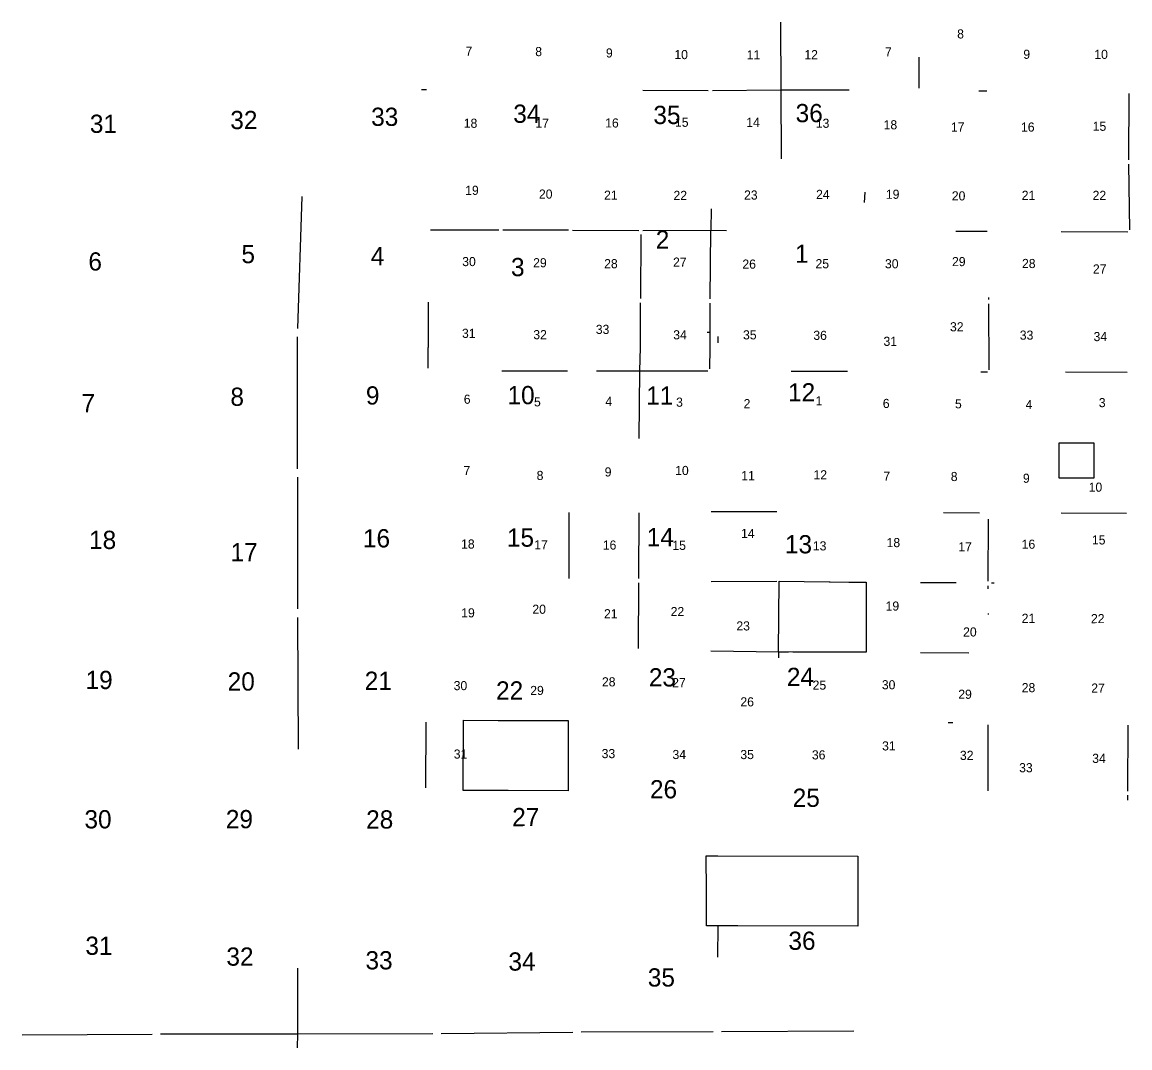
# Model space of a CAD drawing. Extents: x -2251611 to -2054719, y -2227156 to -2099355.
# Drawn here: x -2155950 to -2114262, y -2227040 to -2188443 of the extents above; entities that cross this region are included whole.
import ezdxf

# ---------------------------------------------------------------- set-up
doc = ezdxf.new("R2010")
doc.units = 0
for name, color, linetype in [('tdCoCorpBndry', 7, 'Continuous'), ('tdCoSectLinePart', 7, 'Continuous'), ('tdCoSectNmbr', 7, 'Continuous')]:
    doc.layers.add(name, color=color, linetype=linetype)

msp = doc.modelspace()

# ---------------------------------------------------------------- linework, layer by layer
at = {"layer": 'tdCoCorpBndry'}
for points in [[(-2116923, -2204273), (-2116554, -2204272), (-2116373, -2204271), (-2116187, -2204271), (-2115793, -2204271), (-2115620, -2204270), (-2115612, -2204270), (-2115614, -2205600), (-2116925, -2205597), (-2116926, -2204929), (-2116926, -2204752), (-2116925, -2204568), (-2116924, -2204386)], [(-2127462, -2209483), (-2125572, -2209504), (-2125548, -2209505), (-2125542, -2209505), (-2125537, -2209505), (-2124834, -2209517), (-2124190, -2209521), (-2124191, -2212150), (-2124838, -2212147), (-2126942, -2212144), (-2127479, -2212137), (-2127467, -2210795)], [(-2139345, -2214711), (-2138030, -2214717), (-2135399, -2214723), (-2135403, -2217364), (-2137663, -2217360), (-2137849, -2217360), (-2138035, -2217360), (-2139355, -2217351)], [(-2130202, -2219808), (-2129771, -2219810), (-2124498, -2219826), (-2124500, -2221125), (-2124496, -2222464), (-2129021, -2222452), (-2130200, -2222449), (-2130199, -2221152)]]:
    msp.add_lwpolyline(points, close=True, dxfattribs=at)
at = {"layer": 'tdCoSectLinePart'}
for points in [[(-2127404, -2188443), (-2127393, -2190994)], [(-2122186, -2190931), (-2122189, -2189765)], [(-2140920, -2190981), (-2140735, -2190981)], [(-2132589, -2191000), (-2130131, -2191011)], [(-2129973, -2191011), (-2127393, -2190994)], [(-2127393, -2190994), (-2124824, -2190987)], [(-2127393, -2190994), (-2127387, -2193583)], [(-2119945, -2191028), (-2119639, -2191030)], [(-2114304, -2193622), (-2114291, -2191133)], [(-2114262, -2196262), (-2114303, -2193781)], [(-2124236, -2194846), (-2124256, -2195228)], [(-2145579, -2199969), (-2145406, -2195008)], [(-2130025, -2195473), (-2130029, -2196274)], [(-2140581, -2196261), (-2138013, -2196257)], [(-2137855, -2196257), (-2135392, -2196264)], [(-2135234, -2196265), (-2132745, -2196285)], [(-2132667, -2196438), (-2132683, -2198848)], [(-2132587, -2196285), (-2130029, -2196274)], [(-2130051, -2198859), (-2130029, -2196274)], [(-2130029, -2196274), (-2129444, -2196282)], [(-2120813, -2196307), (-2119638, -2196314)], [(-2116850, -2196318), (-2114333, -2196332)], [(-2140665, -2201458), (-2140664, -2200703), (-2140663, -2200661), (-2140658, -2198979)], [(-2132706, -2201565), (-2132682, -2200687), (-2132682, -2200651), (-2132682, -2200598), (-2132684, -2199007)], [(-2130068, -2201484), (-2130058, -2200702), (-2130060, -2200646), (-2130052, -2199017)], [(-2119570, -2198881), (-2119570, -2198799)], [(-2119551, -2201528), (-2119570, -2199039)], [(-2130175, -2200105), (-2130056, -2200103)], [(-2129765, -2200268), (-2129766, -2200505)], [(-2145581, -2205254), (-2145584, -2200286)], [(-2137902, -2201560), (-2135420, -2201564)], [(-2134332, -2201565), (-2132706, -2201565)], [(-2132729, -2204105), (-2132706, -2201565)], [(-2132706, -2201565), (-2130142, -2201558)], [(-2127009, -2201576), (-2124882, -2201574)], [(-2119871, -2201601), (-2119620, -2201602)], [(-2116681, -2201605), (-2114358, -2201614)], [(-2145581, -2205570), (-2145581, -2210525)], [(-2135369, -2209378), (-2135363, -2206899)], [(-2132744, -2209381), (-2132732, -2206904)], [(-2130022, -2206855), (-2127545, -2206860)], [(-2121277, -2206892), (-2119925, -2206903)], [(-2116852, -2206913), (-2114383, -2206914)], [(-2119589, -2209477), (-2119579, -2207142)], [(-2132753, -2212013), (-2132745, -2209539)], [(-2130017, -2209495), (-2127543, -2209484)], [(-2122144, -2209523), (-2120798, -2209533)], [(-2119589, -2209763), (-2119589, -2209649)], [(-2119468, -2209541), (-2119373, -2209542)], [(-2119587, -2210737), (-2119587, -2210689)], [(-2145581, -2210841), (-2145565, -2215804)], [(-2130035, -2212095), (-2127468, -2212143)], [(-2127469, -2212365), (-2127468, -2212143)], [(-2127468, -2212143), (-2127468, -2212137)], [(-2127468, -2212143), (-2127114, -2212143)], [(-2122138, -2212158), (-2120323, -2212174)], [(-2140752, -2214786), (-2140769, -2217261)], [(-2121100, -2214797), (-2120929, -2214798)], [(-2119600, -2217363), (-2119596, -2214888)], [(-2114334, -2217376), (-2114331, -2214895)], [(-2114335, -2217720), (-2114334, -2217534)], [(-2129774, -2222450), (-2129777, -2223633)], [(-2145580, -2226511), (-2145578, -2224042)], [(-2155950, -2226544), (-2151058, -2226519)], [(-2150741, -2226517), (-2145580, -2226511)], [(-2145590, -2227040), (-2145580, -2226511)], [(-2145580, -2226511), (-2140496, -2226498)], [(-2140179, -2226496), (-2135224, -2226444)], [(-2134909, -2226442), (-2129943, -2226428)], [(-2129627, -2226427), (-2124651, -2226402)]]:
    msp.add_lwpolyline(points, dxfattribs=at)

# ---------------------------------------------------------------- texts
at = {"layer": 'tdCoSectNmbr'}
for s, height, rotation, p in [('8', 343, 0.0063, (-2120761, -2189057)), ('7', 343, 0.0009, (-2139261, -2189704)), ('8', 343, 0.0017, (-2136639, -2189722)), ('9', 343, 0.0024, (-2133979, -2189773)), ('7', 343, 0.0055, (-2123478, -2189734)), ('10', 343.2, 0.0032, (-2131404, -2189834)), ('11', 343.2, 0.004, (-2128683, -2189846)), ('12', 343.2, 0.0046, (-2126511, -2189837)), ('9', 343, 0.007, (-2118271, -2189823)), ('10', 343.2, 0.0078, (-2115599, -2189825)), ('36', 686.4, 0.0197, (-2126839, -2192208)), ('31', 686.4, 0.0158, (-2153401, -2192610)), ('32', 686.4, 0.0166, (-2148117, -2192468)), ('33', 686.4, 0.0174, (-2142815, -2192347)), ('34', 686.4, 0.0182, (-2137467, -2192232)), ('35', 686.4, 0.0189, (-2132193, -2192277)), ('18', 343.2, 0.0008, (-2139330, -2192418)), ('17', 343.2, 0.0016, (-2136633, -2192418)), ('16', 343.2, 0.0024, (-2134008, -2192407)), ('15', 343.2, 0.0032, (-2131381, -2192381)), ('14', 343.2, 0.0039, (-2128697, -2192382)), ('13', 343.2, 0.0047, (-2126081, -2192418)), ('18', 343.2, 0.0054, (-2123528, -2192477)), ('17', 343.2, 0.0062, (-2120996, -2192560)), ('16', 343.2, 0.007, (-2118359, -2192560)), ('15', 343.2, 0.0077, (-2115661, -2192532)), ('19', 343.2, 0.0009, (-2139277, -2194942)), ('20', 343.2, 0.0016, (-2136501, -2195084)), ('21', 343.2, 0.0024, (-2134050, -2195126)), ('22', 343.2, 0.0031, (-2131437, -2195134)), ('23', 343.2, 0.0039, (-2128782, -2195120)), ('24', 343.2, 0.0047, (-2126071, -2195097)), ('19', 343.2, 0.0055, (-2123444, -2195091)), ('20', 343.2, 0.0062, (-2120962, -2195151)), ('21', 343.2, 0.0069, (-2118331, -2195129)), ('22', 343.2, 0.0077, (-2115664, -2195133)), ('2', 686, 0.0188, (-2132104, -2196969)), ('5', 686, 0.0166, (-2147697, -2197513)), ('4', 686, 0.0173, (-2142832, -2197591)), ('1', 686, 0.0196, (-2126864, -2197499)), ('6', 686, 0.0157, (-2153457, -2197790)), ('30', 343.2, 0.0008, (-2139388, -2197624)), ('3', 686, 0.018, (-2137552, -2198002)), ('29', 343.2, 0.0016, (-2136719, -2197668)), ('27', 343.2, 0.0032, (-2131453, -2197645)), ('29', 343.2, 0.0062, (-2120955, -2197625)), ('28', 343.2, 0.0069, (-2118321, -2197696)), ('28', 343.2, 0.0024, (-2134047, -2197703)), ('26', 343.2, 0.0039, (-2128845, -2197719)), ('25', 343.2, 0.0047, (-2126092, -2197704)), ('30', 343.2, 0.0054, (-2123478, -2197707)), ('27', 343.2, 0.0077, (-2115652, -2197903)), ('33', 343.2, 0.0024, (-2134362, -2200176)), ('32', 343.2, 0.0062, (-2121031, -2200078)), ('31', 343.2, 0.0008, (-2139397, -2200324)), ('32', 343.2, 0.0016, (-2136713, -2200374)), ('34', 343.2, 0.0031, (-2131446, -2200380)), ('35', 343.2, 0.0039, (-2128820, -2200381)), ('36', 343.2, 0.0047, (-2126175, -2200399)), ('33', 343.2, 0.0069, (-2118404, -2200392)), ('34', 343.2, 0.0077, (-2115628, -2200446)), ('31', 343.2, 0.0054, (-2123534, -2200624)), ('8', 686, 0.0164, (-2148112, -2202881)), ('9', 686, 0.0172, (-2143012, -2202833)), ('10', 686.4, 0.0179, (-2137684, -2202820)), ('11', 686.4, 0.0187, (-2132465, -2202836)), ('12', 686.4, 0.0195, (-2127126, -2202716)), ('7', 686, 0.0156, (-2153715, -2203122)), ('6', 343, 0.0008, (-2139329, -2202802)), ('5', 343, 0.0016, (-2136686, -2202902)), ('4', 343, 0.0023, (-2134001, -2202884)), ('3', 343, 0.0032, (-2131338, -2202914)), ('2', 343, 0.0039, (-2128798, -2202970)), ('1', 343, 0.0046, (-2126088, -2202864)), ('6', 343, 0.0054, (-2123560, -2202962)), ('5', 343, 0.0062, (-2120843, -2202976)), ('4', 343, 0.0069, (-2118186, -2203003)), ('3', 343, 0.0077, (-2115430, -2202931)), ('7', 343, 0.0008, (-2139339, -2205487)), ('9', 343, 0.0023, (-2134025, -2205538)), ('10', 343.2, 0.0031, (-2131375, -2205485)), ('8', 343, 0.0016, (-2136587, -2205672)), ('11', 343.2, 0.0038, (-2128886, -2205678)), ('12', 343.2, 0.0046, (-2126168, -2205647)), ('7', 343, 0.0054, (-2123535, -2205698)), ('8', 343, 0.0061, (-2121001, -2205712)), ('9', 343, 0.0069, (-2118286, -2205777)), ('10', 343.2, 0.0077, (-2115812, -2206113)), ('18', 686.4, 0.0155, (-2153432, -2208268)), ('16', 686.4, 0.0171, (-2143124, -2208209)), ('15', 686.4, 0.0178, (-2137706, -2208182)), ('14', 686.4, 0.0186, (-2132442, -2208162)), ('14', 343.2, 0.0038, (-2128894, -2207854)), ('13', 686.4, 0.0193, (-2127243, -2208433)), ('15', 343.2, 0.0076, (-2115689, -2208098)), ('17', 686.4, 0.0163, (-2148107, -2208730)), ('18', 343.2, 0.0007, (-2139431, -2208252)), ('17', 343.2, 0.0015, (-2136676, -2208280)), ('16', 343.2, 0.0022, (-2134097, -2208291)), ('15', 343.2, 0.003, (-2131480, -2208303)), ('13', 343.2, 0.0046, (-2126192, -2208322)), ('18', 343.2, 0.0053, (-2123417, -2208199)), ('17', 343.2, 0.0062, (-2120717, -2208356)), ('16', 343.2, 0.0068, (-2118334, -2208259)), ('19', 343.2, 0.0053, (-2123453, -2210586)), ('19', 343.2, 0.0007, (-2139426, -2210842)), ('20', 343.2, 0.0015, (-2136748, -2210706)), ('21', 343.2, 0.0023, (-2134053, -2210876)), ('22', 343.2, 0.003, (-2131544, -2210794)), ('23', 343.2, 0.0038, (-2129070, -2211333)), ('21', 343.2, 0.0068, (-2118333, -2211047)), ('22', 343.2, 0.0076, (-2115726, -2211059)), ('20', 343.2, 0.0062, (-2120537, -2211561)), ('23', 686.4, 0.0185, (-2132364, -2213440)), ('24', 686.4, 0.0193, (-2127171, -2213424)), ('19', 686.4, 0.0155, (-2153563, -2213539)), ('20', 686.4, 0.0162, (-2148215, -2213596)), ('21', 686.4, 0.017, (-2143056, -2213569)), ('28', 343.2, 0.0022, (-2134130, -2213438)), ('27', 343.2, 0.003, (-2131485, -2213469)), ('30', 343.2, 0.0007, (-2139710, -2213580)), ('22', 686.4, 0.0178, (-2138114, -2213935)), ('29', 343.2, 0.0015, (-2136828, -2213763)), ('25', 343.2, 0.0045, (-2126201, -2213563)), ('30', 343.2, 0.0053, (-2123596, -2213548)), ('29', 343.2, 0.0061, (-2120719, -2213905)), ('28', 343.2, 0.0068, (-2118331, -2213656)), ('27', 343.2, 0.0075, (-2115714, -2213673)), ('26', 343.2, 0.0037, (-2128919, -2214191)), ('31', 343.2, 0.0053, (-2123586, -2215849)), ('31', 343.2, 0.0006, (-2139707, -2216156)), ('33', 343.2, 0.0022, (-2134141, -2216138)), ('34', 343.2, 0.003, (-2131475, -2216173)), ('35', 343.2, 0.0037, (-2128920, -2216174)), ('36', 343.2, 0.0045, (-2126228, -2216186)), ('32', 343.2, 0.0061, (-2120657, -2216205)), ('34', 343.2, 0.0075, (-2115679, -2216318)), ('33', 343.2, 0.0068, (-2118429, -2216670)), ('26', 686.4, 0.0184, (-2132322, -2217651)), ('25', 686.4, 0.0192, (-2126950, -2217973)), ('30', 686.4, 0.0153, (-2153605, -2218782)), ('29', 686.4, 0.0161, (-2148284, -2218776)), ('28', 686.4, 0.0169, (-2143004, -2218787)), ('27', 686.4, 0.0177, (-2137507, -2218698)), ('36', 686.4, 0.0191, (-2127111, -2223352)), ('31', 686.4, 0.0153, (-2153570, -2223540)), ('32', 686.4, 0.0161, (-2148263, -2223948)), ('33', 686.4, 0.0168, (-2143028, -2224088)), ('34', 686.4, 0.0176, (-2137649, -2224134)), ('35', 686.4, 0.0183, (-2132404, -2224734))]:
    msp.add_text(s, height=height, rotation=rotation, dxfattribs=at).set_placement(p)

doc.saveas('drawing.dxf')
